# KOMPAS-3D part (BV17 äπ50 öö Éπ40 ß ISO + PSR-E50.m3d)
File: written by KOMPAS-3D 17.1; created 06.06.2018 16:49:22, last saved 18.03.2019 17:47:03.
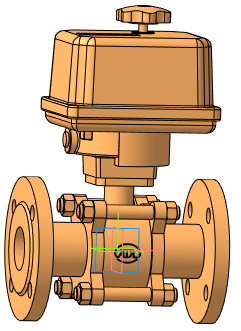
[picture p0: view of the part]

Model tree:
1. Операция без истории:2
